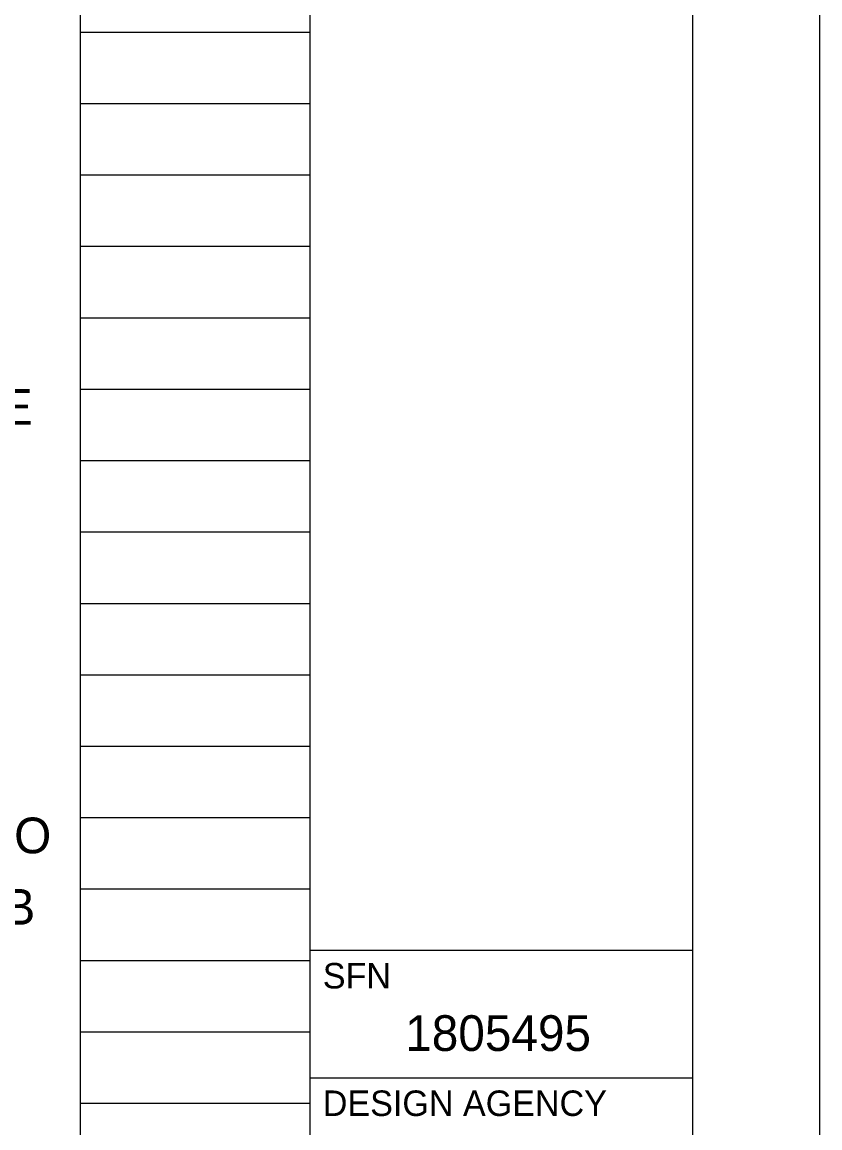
# Model space of a CAD drawing. Extents: x 0 to 34, y 0 to 22.
# Drawn here: x 30.87 to 34, y 4.803 to 9.139 of the extents above; entities that cross this region are included whole.
import ezdxf

# ---------------------------------------------------------------- set-up
doc = ezdxf.new("R2010")
doc.units = 0
for name, color, linetype in [('BR_P_Gen_Text', 7, 'Continuous'), ('SH_Border', 7, 'Continuous'), ('SH_Cut_Line', 7, 'Continuous'), ('SH_Data', 7, 'Continuous')]:
    doc.layers.add(name, color=color, linetype=linetype)

msp = doc.modelspace()

# ---------------------------------------------------------------- linework, layer by layer
at = {"layer": 'SH_Border'}
for p, q in [((32, 0.5), (32, 21.5)), ((32, 5.5), (33.5, 5.5)), ((32, 5), (33.5, 5))]:
    msp.add_line(p, q, dxfattribs=at)
msp.add_lwpolyline([(1.5, 21.5), (33.5, 21.5), (33.5, 0.5), (1.5, 0.5)], close=True, dxfattribs=at)
at = {"layer": 'SH_Cut_Line'}
msp.add_lwpolyline([(0, 0), (34, 0), (34, 22), (0, 22)], close=True, dxfattribs=at)
at = {"layer": 'SH_Data'}
for p, q in [((31.1, 0.98), (31.1, 21.14)), ((32, 0.98), (32, 21.14)), ((31.1, 9.1), (32, 9.1)), ((31.1, 8.82), (32, 8.82)), ((31.1, 8.54), (32, 8.54)), ((31.1, 8.26), (32, 8.26)), ((31.1, 7.98), (32, 7.98)), ((31.1, 7.7), (32, 7.7)), ((31.1, 7.42), (32, 7.42)), ((31.1, 7.14), (32, 7.14)), ((31.1, 6.86), (32, 6.86)), ((31.1, 6.58), (32, 6.58)), ((31.1, 6.3), (32, 6.3)), ((31.1, 6.02), (32, 6.02)), ((31.1, 5.74), (32, 5.74)), ((31.1, 5.46), (32, 5.46)), ((31.1, 5.18), (32, 5.18)), ((31.1, 4.9), (32, 4.9))]:
    msp.add_line(p, q, dxfattribs=at)

# ---------------------------------------------------------------- texts
at = {"layer": 'BR_P_Gen_Text'}
for s, p in [('METHOD OF MEASUREMENT: THE LENGTH MEASURED WILL BE THE ', (24.66, 7.56)), ('MATERIALS, LABOR, EQUIPMENT, AND INCIDENTALS NECESSARY TO ', (24.66, 5.88)), ('FURNISH AND INSTALL THE VANDAL PROTECTION FENCE WITH RUB ', (24.66, 5.6))]:
    msp.add_text(s, height=0.14, dxfattribs=at).set_placement(p)
at = {"layer": 'SH_Data'}
for s, height, p in [('SFN', 0.1, (32.05, 5.35)), ('1805495', 0.14, (32.3733, 5.105)), ('DESIGN AGENCY', 0.1, (32.05, 4.85))]:
    msp.add_text(s, height=height, dxfattribs=at).set_placement(p)

doc.saveas('drawing.dxf')
